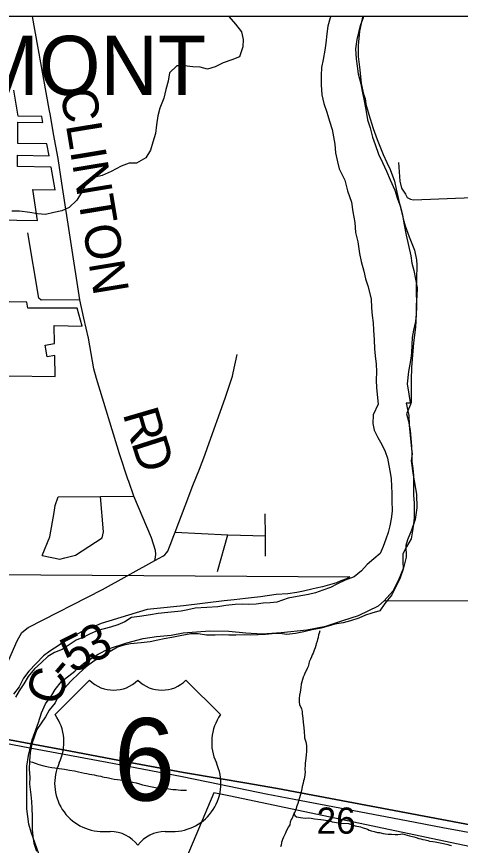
# Model space of a CAD drawing. Extents: x -8.5 to 18.7, y -20.3 to 7.
# Drawn here: x -4.185 to -2.768, y 4.29 to 6.938 of the extents above; entities that cross this region are included whole.
import ezdxf

# ---------------------------------------------------------------- set-up
doc = ezdxf.new("R2010")
doc.units = 0
for name, color, linetype in [('Default', 7, 'Continuous'), ('GM_X_City_Street', 7, 'Continuous'), ('GM_X_Corporation', 7, 'Continuous'), ('GM_X_Corporation_Text', 7, 'Continuous'), ('GM_X_County_Road', 7, 'Continuous'), ('GM_X_County_Road_Text', 7, 'Continuous'), ('GM_X_Major_River', 7, 'Continuous'), ('GM_X_Minor_River', 7, 'Continuous'), ('GM_X_Section', 7, 'Continuous'), ('GM_X_Section_Text', 7, 'Continuous'), ('GM_X_State_Route', 7, 'Continuous'), ('GM_X_Township_Road', 7, 'Continuous'), ('GM_X_US_Location', 7, 'Continuous'), ('GM_X_US_Route', 7, 'Continuous'), ('GM_X_US_Shield', 7, 'Continuous'), ('SH_Cut_Line', 7, 'Continuous')]:
    doc.layers.add(name, color=color, linetype=linetype)

msp = doc.modelspace()

# ---------------------------------------------------------------- linework, layer by layer
at = {"layer": 'Default'}
msp.add_lwpolyline([(-2.1387, 6.938), (-3.0796, 6.938), (-3.082, 6.9308), (-3.0906, 6.8915), (-3.0947, 6.846), (-3.0949, 6.8104), (-3.0899, 6.7679), (-3.0848, 6.7239), (-3.0775, 6.6905), (-3.073, 6.6761), (-3.0701, 6.6586), (-3.0604, 6.6252), (-3.0471, 6.5804), (-3.0344, 6.5455), (-3.015, 6.4976), (-3.003, 6.4717), (-2.9926, 6.4489), (-2.9791, 6.4117), (-2.9732, 6.3867), (-2.9659, 6.3533), (-2.96, 6.3267), (-2.9496, 6.2842), (-2.9444, 6.2697), (-2.9325, 6.234), (-2.9153, 6.1915), (-2.9087, 6.1611), (-2.908, 6.1452), (-2.9083, 6.0975), (-2.9092, 6.0724), (-2.9089, 6.008), (-2.9123, 5.9451), (-2.9187, 5.8951), (-2.922, 5.8436), (-2.9245, 5.8171), (-2.9255, 5.7777), (-2.9259, 5.7163), (-2.9252, 5.7026), (-2.9416, 5.7024), (-2.9327, 5.6637), (-2.9322, 5.6326), (-2.9243, 5.5567), (-2.9221, 5.5408), (-2.9253, 5.5181), (-2.9188, 5.4726), (-2.9085, 5.4118), (-2.9073, 5.3679), (-2.9128, 5.3315), (-2.9244, 5.2967), (-2.9375, 5.2665), (-2.9429, 5.2476), (-2.9416, 5.2104), (-2.9502, 5.1764), (-2.9671, 5.1355), (-2.9847, 5.1023), (-3.0114, 5.0714), (-2.2011, 5.074)], dxfattribs=at)
at = {"layer": 'GM_X_City_Street'}
for points in [[(-4.2512, 6.2886), (-4.1182, 6.2863), (-4.134, 6.3858), (-4.0618, 6.3844), (-4.0749, 6.4565), (-4.1821, 6.4584), (-4.1821, 6.4955), (-4.0818, 6.4935), (-4.0887, 6.5311), (-4.1813, 6.5328), (-4.1813, 6.601), (-4.1014, 6.5997), (-4.1049, 6.6189), (-4.1809, 6.6201), (-4.194, 6.7024)], [(-4.2097, 5.7905), (-4.0623, 5.788), (-4.0635, 5.8554), (-4.0882, 5.8511), (-4.0941, 5.8885), (-4.0642, 5.8938), (-4.0653, 5.9506), (-3.9758, 5.9491), (-3.9919, 6.0062), (-4.1498, 6.0064), (-4.1528, 6.0255), (-4.2096, 6.0265)], [(-2.7206, 4.2815), (-3.5022, 4.4472), (-3.5552, 4.4573), (-3.6617, 4.2047)]]:
    msp.add_lwpolyline(points, dxfattribs=at)
at = {"layer": 'GM_X_Corporation'}
msp.add_lwpolyline([(-0.1911, 6.938), (-8.4587, 6.938), (-8.4587, 1.1732)], dxfattribs=at)
at = {"layer": 'GM_X_County_Road'}
for p, q in [((-4.0811, 6.6417), (-4.1343, 6.938)), ((-4.0776, 6.6221), (-4.0811, 6.6417)), ((-4.0671, 6.5632), (-4.0776, 6.6221)), ((-4.06, 6.524), (-4.0671, 6.5632)), ((-4.053, 6.4848), (-4.06, 6.524)), ((-4.041, 6.4062), (-4.053, 6.4848)), ((-3.9839, 6.0329), (-4.041, 6.4062)), ((-3.9706, 5.9747), (-3.9839, 6.0329))]:
    msp.add_line(p, q, dxfattribs=at)
for points in [[(-3.9299, 5.7817), (-3.939, 5.812), (-3.9558, 5.9108), (-3.9706, 5.9747)], [(-3.8298, 5.4598), (-3.8574, 5.5413), (-3.9299, 5.7817)], [(-4.2363, 4.8324), (-4.2176, 4.8653), (-4.1837, 4.9433), (-4.1688, 4.9696), (-4.1488, 4.986), (-3.9115, 5.1068), (-3.7446, 5.2003), (-3.7418, 5.2105), (-3.7408, 5.2204), (-3.7415, 5.2315), (-3.7547, 5.2723), (-3.8114, 5.4057), (-3.8272, 5.4522), (-3.8298, 5.4598)]]:
    msp.add_lwpolyline(points, dxfattribs=at)
at = {"layer": 'GM_X_Major_River'}
for points in [[(-3.1825, 6.938), (-3.184, 6.9335), (-3.1913, 6.907), (-3.1948, 6.8827), (-3.1984, 6.8531), (-3.2018, 6.8303), (-3.2062, 6.8007), (-3.2119, 6.7757), (-3.2131, 6.7498), (-3.2129, 6.7194), (-3.2112, 6.6874), (-3.2048, 6.6598), (-3.1947, 6.6322), (-3.186, 6.6039), (-3.1774, 6.5771), (-3.1698, 6.5298), (-3.1673, 6.5031), (-3.1609, 6.474), (-3.1552, 6.4511), (-3.1376, 6.4157), (-3.1291, 6.3813), (-3.116, 6.3453), (-3.112, 6.314), (-3.1057, 6.2804), (-3.1033, 6.2476), (-3.0962, 6.2185), (-3.0908, 6.1811), (-3.0851, 6.1559), (-3.0765, 6.1245), (-3.0716, 6.1), (-3.0644, 6.0771), (-3.053, 6.0357), (-3.0527, 6.0076), (-3.0501, 5.9831), (-3.0475, 5.9595), (-3.0456, 5.9359), (-3.0439, 5.9054), (-3.0429, 5.8764), (-3.0402, 5.8535), (-3.0376, 5.8276), (-3.0365, 5.804), (-3.0378, 5.7766), (-3.0367, 5.7515), (-3.0307, 5.6993)], [(-3.0774, 6.938), (-3.079, 6.9338), (-3.087, 6.9111), (-3.0935, 6.8869), (-3.0992, 6.8642), (-3.1036, 6.8353), (-3.1011, 6.8033), (-3.0984, 6.7796), (-3.0951, 6.7552), (-3.0865, 6.7231), (-3.0816, 6.6994), (-3.0753, 6.6688), (-3.069, 6.6344)], [(-3.069, 6.6344), (-3.0649, 6.6085), (-3.057, 6.5824), (-3.0492, 6.5526), (-3.0405, 6.5296), (-3.0296, 6.4982), (-3.0171, 6.4721), (-3.0047, 6.4437), (-2.993, 6.416), (-2.9783, 6.383), (-2.9704, 6.3593), (-2.9595, 6.3301), (-2.9531, 6.3034), (-2.9476, 6.2728), (-2.9413, 6.2399), (-2.9343, 6.2063), (-2.9265, 6.1734), (-2.9231, 6.1505), (-2.9174, 6.1261), (-2.9118, 6.0985), (-2.907, 6.071), (-2.9074, 6.0452), (-2.9095, 6.0155), (-2.9092, 5.9873), (-2.9119, 5.9638), (-2.9177, 5.9365), (-2.922, 5.913), (-2.9231, 5.8894), (-2.9251, 5.8628), (-2.9278, 5.8392), (-2.9338, 5.8036), (-2.9383, 5.7648), (-2.9281, 5.6987)], [(-3.0307, 5.6993), (-3.047, 5.6654), (-3.048, 5.6381), (-3.0437, 5.6167), (-3.0319, 5.5931), (-3.0192, 5.5709), (-3.0089, 5.5488), (-3.0015, 5.5267), (-2.9972, 5.5031), (-2.9922, 5.4811), (-2.9894, 5.4605), (-2.9881, 5.4377), (-2.9876, 5.4142), (-2.9871, 5.3914), (-2.986, 5.358), (-2.9893, 5.333), (-2.9933, 5.311), (-2.9989, 5.289), (-3.0067, 5.2679), (-3.0153, 5.2452), (-3.0247, 5.2225), (-3.0454, 5.2053), (-3.0661, 5.1873), (-3.0845, 5.167), (-3.1075, 5.1482), (-3.1364, 5.1371), (-3.1631, 5.1245), (-3.1837, 5.1141), (-3.2081, 5.1053), (-3.231, 5.0971), (-3.253, 5.0913), (-3.2895, 5.0849), (-3.3184, 5.0799), (-3.355, 5.0666), (-3.3762, 5.0645), (-3.3983, 5.064), (-3.4203, 5.0605), (-3.4438, 5.0592), (-3.4651, 5.0602), (-3.4878, 5.0597), (-3.5175, 5.0562), (-3.5433, 5.0519), (-3.5782, 5.05), (-3.6154, 5.0473), (-3.639, 5.0423), (-3.6595, 5.0379), (-3.6816, 5.0359), (-3.7028, 5.0339), (-3.7332, 5.0304), (-3.7583, 5.0269), (-3.7925, 5.0211), (-3.8183, 5.0176), (-3.8397, 5.0042), (-3.8626, 4.9946), (-3.8854, 4.9872), (-3.906, 4.9821), (-3.9265, 4.9763), (-3.9502, 4.9659), (-3.9723, 4.9547), (-3.9952, 4.9451), (-4.0181, 4.9302), (-4.0403, 4.916), (-4.0639, 4.9064), (-4.0853, 4.8937), (-4.106, 4.8742), (-4.1282, 4.8539), (-4.1482, 4.8291), (-4.1621, 4.8064), (-4.1768, 4.7838), (-4.1884, 4.7634)], [(-2.9281, 5.6987), (-2.9407, 5.6688), (-2.9342, 5.6452), (-2.9292, 5.6155), (-2.9264, 5.5904), (-2.9245, 5.5638), (-2.924, 5.5395), (-2.9235, 5.5168), (-2.9199, 5.4939), (-2.9187, 5.4719), (-2.9182, 5.4499), (-2.9184, 5.4294), (-2.9179, 5.4074), (-2.9166, 5.3846), (-2.9162, 5.3603), (-2.9164, 5.3367), (-2.9182, 5.3163), (-2.9215, 5.295), (-2.9255, 5.2693), (-2.9402, 5.2436), (-2.9519, 5.2217), (-2.9521, 5.1982), (-2.9509, 5.1724), (-2.9611, 5.1451), (-2.9712, 5.1225), (-2.9875, 5.0908), (-3.0098, 5.0629), (-3.026, 5.0395), (-3.0512, 5.0315), (-3.0717, 5.0256), (-3.0931, 5.0152), (-3.1189, 5.0071), (-3.1425, 5.0013), (-3.1699, 4.997), (-3.1905, 4.9897), (-3.2125, 4.9838), (-3.2414, 4.9781), (-3.268, 4.9723), (-3.2954, 4.9665), (-3.3228, 4.9637), (-3.3447, 4.9663), (-3.3698, 4.9658), (-3.3903, 4.9637), (-3.4146, 4.9624), (-3.4374, 4.9619), (-3.4586, 4.9622), (-3.4852, 4.9609), (-3.5079, 4.9619), (-3.5292, 4.9622), (-3.5512, 4.9616), (-3.5792, 4.9619), (-3.6057, 4.9652), (-3.6293, 4.9655), (-3.6627, 4.959), (-3.6901, 4.954), (-3.7144, 4.9497), (-3.7349, 4.9454), (-3.7593, 4.9396), (-3.7881, 4.9368), (-3.8216, 4.9341), (-3.8428, 4.9298), (-3.8634, 4.9232), (-3.8863, 4.909), (-3.9154, 4.8919), (-3.939, 4.8785), (-3.9628, 4.8597), (-3.9857, 4.8395), (-4.0118, 4.8147), (-4.0326, 4.7921), (-4.0503, 4.7696), (-4.0627, 4.7454), (-4.0819, 4.7221), (-4.0935, 4.7009), (-4.1074, 4.6806), (-4.1206, 4.6595), (-4.1284, 4.6383), (-4.137, 4.6141), (-4.1419, 4.5868), (-4.1445, 4.5602), (-4.1455, 4.5322), (-4.1435, 4.5079), (-4.1445, 4.4851), (-4.1404, 4.4516), (-4.1383, 4.4304), (-4.1363, 4.4083), (-4.1359, 4.3825), (-4.1353, 4.3612), (-4.1356, 4.3407), (-4.1336, 4.3179), (-4.13, 4.2966), (-4.1219, 4.2707)]]:
    msp.add_lwpolyline(points, dxfattribs=at)
at = {"layer": 'GM_X_Minor_River'}
for points in [[(-3.5078, 6.938), (-3.4864, 6.914), (-3.4676, 6.8896), (-3.4617, 6.8644), (-3.4626, 6.8409), (-3.4742, 6.8098), (-3.4978, 6.8001), (-3.526, 6.7897), (-3.5511, 6.777), (-3.5762, 6.7696), (-3.5997, 6.7766), (-3.6232, 6.7776), (-3.6505, 6.7801), (-3.674, 6.7803), (-3.6977, 6.7585), (-3.7017, 6.7311), (-3.7094, 6.7046), (-3.7157, 6.6773), (-3.7281, 6.6455), (-3.7343, 6.6212), (-3.7391, 6.5923), (-3.7423, 6.5642), (-3.7501, 6.5369), (-3.7579, 6.5112), (-3.7732, 6.4862), (-3.8022, 6.4697), (-3.8265, 6.4699), (-3.8516, 6.4603), (-3.8836, 6.4431), (-3.9125, 6.4304), (-3.9391, 6.4238), (-3.9628, 6.4034), (-3.9782, 6.3754), (-3.9927, 6.3512), (-4.0172, 6.3279), (-4.0408, 6.3174), (-4.0666, 6.3123), (-4.0932, 6.3057), (-4.119, 6.3074), (-4.1433, 6.3122), (-4.1759, 6.3163), (-4.2001, 6.3157)], [(-3.2178, 4.9756), (-3.2195, 4.9673), (-3.2211, 4.962), (-3.2228, 4.9544), (-3.2252, 4.9476), (-3.2261, 4.9423), (-3.2293, 4.9333), (-3.2301, 4.928), (-3.2326, 4.9205), (-3.235, 4.9137), (-3.239, 4.9039), (-3.2414, 4.8987), (-3.2438, 4.8926), (-3.247, 4.8843), (-3.2509, 4.8761), (-3.2526, 4.8693), (-3.255, 4.861), (-3.2582, 4.855), (-3.2614, 4.8475), (-3.2653, 4.8399), (-3.2677, 4.8332), (-3.2701, 4.8271), (-3.275, 4.8121), (-3.2766, 4.8053), (-3.2784, 4.7939), (-3.2802, 4.7788), (-3.2827, 4.7697), (-3.2836, 4.7591), (-3.283, 4.7523), (-3.2831, 4.747), (-3.2818, 4.7394), (-3.276, 4.7256), (-3.2739, 4.718), (-3.274, 4.7111), (-3.2713, 4.6959), (-3.2701, 4.6822), (-3.2695, 4.6746), (-3.2669, 4.6548), (-3.267, 4.648), (-3.2664, 4.6419), (-3.2666, 4.6336), (-3.2644, 4.6275), (-3.2623, 4.6206), (-3.2595, 4.6084), (-3.2599, 4.5895), (-3.2609, 4.5789), (-3.2628, 4.5592), (-3.2637, 4.5539), (-3.2638, 4.5486), (-3.2649, 4.5311), (-3.2643, 4.5251), (-3.2652, 4.5152), (-3.267, 4.5016), (-3.2694, 4.4956), (-3.2703, 4.4888), (-3.2736, 4.4782), (-3.2745, 4.4706), (-3.2794, 4.4525), (-3.2835, 4.4382), (-3.2859, 4.4306), (-3.2876, 4.4239), (-3.2899, 4.4186), (-3.2916, 4.4126), (-3.2925, 4.4073), (-3.2964, 4.399), (-3.3028, 4.3847), (-3.3059, 4.3772), (-3.3091, 4.3719), (-3.3123, 4.3636), (-3.3132, 4.3553), (-3.3171, 4.3486), (-3.3242, 4.3373), (-3.3282, 4.3268), (-3.333, 4.3163), (-3.3362, 4.308), (-3.3394, 4.2989), (-3.3403, 4.2906), (-3.3427, 4.2846)], [(-4.1445, 4.5576), (-4.1344, 4.5553), (-4.1261, 4.5528), (-4.1141, 4.548), (-4.0983, 4.5439), (-4.0847, 4.5406), (-4.0734, 4.5381), (-4.0636, 4.5372), (-4.0492, 4.5354), (-4.0326, 4.5335), (-4.016, 4.5302), (-4.0009, 4.5276), (-3.9881, 4.5251), (-3.9783, 4.5226), (-3.9685, 4.5209), (-3.9617, 4.5192), (-3.9527, 4.5175), (-3.9451, 4.5166), (-3.9376, 4.5149), (-3.9308, 4.5133), (-3.924, 4.5124), (-3.9165, 4.5107), (-3.9112, 4.5091), (-3.9059, 4.5082), (-3.8976, 4.5066), (-3.8924, 4.5057), (-3.8833, 4.5032), (-3.8735, 4.5015), (-3.8637, 4.5006), (-3.8546, 4.4996), (-3.8463, 4.4979), (-3.8373, 4.497), (-3.8267, 4.4945), (-3.8154, 4.492), (-3.8033, 4.4895), (-3.7928, 4.4863), (-3.783, 4.483), (-3.7732, 4.4813), (-3.7574, 4.478), (-3.7423, 4.4746), (-3.7265, 4.472), (-3.7106, 4.471), (-3.6993, 4.47), (-3.6925, 4.4691), (-3.6864, 4.4682), (-3.6758, 4.468), (-3.6698, 4.4671), (-3.6607, 4.4662), (-3.6433, 4.4658)], [(-3.3018, 4.3945), (-3.2996, 4.3907), (-3.2975, 4.3854), (-3.2923, 4.3807), (-3.2855, 4.3798), (-3.2794, 4.3789), (-3.2719, 4.378), (-3.262, 4.3771), (-3.2545, 4.3777), (-3.2454, 4.3767), (-3.2341, 4.3742), (-3.2137, 4.3723), (-3.2061, 4.3714), (-3.1858, 4.368), (-3.1782, 4.3648), (-3.1564, 4.3613), (-3.1488, 4.3612), (-3.1254, 4.3592), (-3.1111, 4.3543), (-3.1043, 4.3519), (-3.0877, 4.3493), (-3.0817, 4.3469), (-3.0652, 4.3413), (-3.0599, 4.3381), (-3.0531, 4.3365), (-3.0441, 4.334), (-3.0336, 4.3308), (-3.0268, 4.3306), (-3.0155, 4.3282), (-3.0072, 4.3265), (-2.9996, 4.3256), (-2.9883, 4.3253), (-2.9769, 4.3243), (-2.9678, 4.3249), (-2.9602, 4.3255), (-2.9534, 4.3262), (-2.9459, 4.3245), (-2.9308, 4.3204), (-2.9173, 4.3171), (-2.9097, 4.3154), (-2.9007, 4.3122), (-2.8947, 4.3106), (-2.8879, 4.3089), (-2.8811, 4.3073), (-2.8728, 4.3056), (-2.8668, 4.3032), (-2.8562, 4.3022), (-2.8495, 4.3006), (-2.8336, 4.298), (-2.8276, 4.2971), (-2.8223, 4.2955), (-2.8087, 4.2922), (-2.8027, 4.2905), (-2.7967, 4.2897)]]:
    msp.add_lwpolyline(points, dxfattribs=at)
at = {"layer": 'GM_X_Section'}
for points in [[(-4.2745, 5.1557), (-3.1216, 5.1479), (-3.1285, 5.1426), (-3.1505, 5.1351), (-3.1642, 5.1284), (-3.209, 5.1158), (-3.2287, 5.1121), (-3.2386, 5.1091), (-3.2697, 5.1025), (-3.291, 5.0973), (-3.3198, 5.093), (-3.357, 5.0909), (-3.4063, 5.0836), (-3.4548, 5.0786), (-3.4912, 5.0743), (-3.5231, 5.0707), (-3.6528, 5.0556), (-3.7476, 5.0456), (-3.7681, 5.0434), (-3.8281, 5.0248), (-3.9154, 4.9989), (-3.9778, 4.972), (-4.0013, 4.9592), (-4.0249, 4.948), (-4.0493, 4.9292), (-4.079, 4.9104), (-4.0995, 4.8954), (-4.1461, 4.8464), (-4.1629, 4.8238), (-4.1774, 4.7958), (-4.195, 4.7724)], [(-4.1081, 4.2443), (-4.1394, 4.3324), (-4.1468, 4.3575), (-4.1525, 4.4068), (-4.153, 4.4606), (-4.1532, 4.5425), (-4.1469, 4.5773), (-4.136, 4.6273), (-4.116, 4.6825), (-4.1059, 4.7135), (-4.0929, 4.7422), (-4.073, 4.7694), (-4.0623, 4.7883), (-4.0417, 4.8132), (-3.999, 4.8462), (-3.9708, 4.8719), (-3.9251, 4.9004), (-3.8917, 4.9176), (-3.8332, 4.937), (-3.7816, 4.9503), (-3.7383, 4.9576), (-3.692, 4.9611), (-3.6541, 4.9684), (-3.5684, 4.9755), (-3.5078, 4.9744), (-3.4532, 4.9687), (-3.4009, 4.9661), (-3.341, 4.9695), (-3.2591, 4.9789), (-3.1984, 4.9899), (-3.1437, 5.0085), (-3.0936, 5.0241), (-3.0297, 5.0548), (-3.0114, 5.0714), (-2.2011, 5.074)]]:
    msp.add_lwpolyline(points, dxfattribs=at)
at = {"layer": 'GM_X_State_Route'}
msp.add_lwpolyline([(-2.5151, 4.3134), (-2.5309, 4.3165), (-2.7546, 4.3585), (-3.3528, 4.4711), (-3.4568, 4.4899), (-3.5327, 4.5028), (-3.6527, 4.523), (-3.7428, 4.5391), (-3.8177, 4.5532), (-4.0136, 4.5906), (-4.1567, 4.6172), (-4.2822, 4.6413)], dxfattribs=at)
at = {"layer": 'GM_X_Township_Road'}
for p, q in [((-3.4943, 5.7993), (-3.4815, 5.8585)), ((-3.5438, 5.1647), (-3.5108, 5.2824)), ((-3.3905, 5.2142), (-3.3908, 5.2592))]:
    msp.add_line(p, q, dxfattribs=at)
for points in [[(-2.9656, 6.4716), (-2.9618, 6.4121), (-2.9561, 6.3892), (-2.9442, 6.37), (-2.9385, 6.3603), (-2.9282, 6.3546), (-2.9178, 6.352), (-2.6225, 6.3637), (-2.4066, 6.3758)], [(-3.9839, 6.0329), (-4.1068, 6.0321), (-4.114, 6.0377), (-4.1491, 6.247)], [(-3.6858, 5.2742), (-3.6795, 5.2905), (-3.6473, 5.3743), (-3.6225, 5.4396), (-3.6016, 5.4918), (-3.5848, 5.5361), (-3.5756, 5.5609), (-3.5197, 5.7186), (-3.4965, 5.7895), (-3.4943, 5.7993)], [(-4.1041, 5.2155), (-4.0789, 5.2759), (-4.0655, 5.3532), (-4.0628, 5.3759), (-4.0525, 5.4031)], [(-4.0525, 5.4031), (-3.9177, 5.4046), (-3.8114, 5.4057)], [(-4.0313, 5.2086), (-3.9978, 5.2168), (-3.9126, 5.2725), (-3.9078, 5.2921), (-3.9177, 5.4046)], [(-3.3908, 5.2592), (-3.391, 5.2793), (-3.3915, 5.3492)], [(-3.7446, 5.2003), (-3.7307, 5.2074), (-3.7189, 5.2136), (-3.7125, 5.2183), (-3.7068, 5.2244), (-3.7026, 5.2301), (-3.69, 5.2633), (-3.6858, 5.2742)], [(-3.6795, 5.2905), (-3.5108, 5.2824), (-3.391, 5.2793)], [(-4.1041, 5.2155), (-4.0474, 5.2047), (-4.0313, 5.2086)]]:
    msp.add_lwpolyline(points, dxfattribs=at)
at = {"layer": 'GM_X_US_Route'}
for points in [[(-4.6555, 4.6934), (-4.6282, 4.6899), (-4.5897, 4.6841), (-4.4884, 4.6668), (-4.287, 4.6289), (-4.1658, 4.606), (-4.0572, 4.5855)], [(-4.2822, 4.6413), (-4.1567, 4.6172), (-4.0136, 4.5906), (-3.8177, 4.5532), (-3.7428, 4.5391), (-3.6527, 4.523), (-3.5327, 4.5028), (-3.4568, 4.4899), (-3.3528, 4.4711), (-2.7546, 4.3585), (-2.5309, 4.3165), (-2.5151, 4.3134)], [(-4.0572, 4.5855), (-4.0165, 4.5778), (-3.8966, 4.5554), (-3.807, 4.5384), (-3.6567, 4.5093), (-3.538, 4.4848), (-3.3887, 4.4543), (-3.2995, 4.4369), (-2.9404, 4.3693), (-2.8243, 4.3473)], [(-2.8243, 4.3473), (-2.7604, 4.3352), (-2.5512, 4.296)]]:
    msp.add_lwpolyline(points, dxfattribs=at)
at = {"layer": 'GM_X_US_Shield'}
for p, q in [((-3.9523, 4.8173), (-4.0622, 4.7074)), ((-3.5348, 4.7074), (-3.6447, 4.8173)), ((-3.9084, 4.3339), (-3.8864, 4.3339)), ((-3.7106, 4.3339), (-3.6886, 4.3339))]:
    msp.add_line(p, q, dxfattribs=at)
for centre, radius, start, end in [((-3.8754, 4.8957), 0.1099, 225.573, 314.427), ((-3.7216, 4.8957), 0.1099, 225.573, 314.427), ((-4.1882, 4.6192), 0.1538, 334.5471, 35.0009), ((-3.4088, 4.6192), 0.1538, 144.9991, 205.4529), ((-3.9101, 4.4877), 0.1538, 154.8319, 270.6383), ((-3.6869, 4.4877), 0.1538, 269.3617, 25.1681), ((-3.8864, 4.224), 0.1099, 36.8699, 90), ((-3.7106, 4.224), 0.1099, 90, 143.1301)]:
    msp.add_arc(centre, radius, start, end, dxfattribs=at)
at = {"layer": 'SH_Cut_Line'}
msp.add_lwpolyline([(18.7413, 6.938), (-8.4587, 6.938), (-8.4587, -10.6981)], dxfattribs=at)

# ---------------------------------------------------------------- texts
at = {"layer": 'GM_X_Corporation_Text'}
msp.add_text('FREMONT', height=0.18939, rotation=0, dxfattribs=at).set_placement((-4.8322, 6.6871))
at = {"layer": 'GM_X_County_Road_Text'}
for s, height, rotation, p in [('CLINTON', 0.11364, 279.3643, (-4.0463, 6.7003)), ('R', 0.1136, 286.3239, (-3.8472, 5.6692)), ('D', 0.1136, 287.7514, (-3.8201, 5.5767)), ('3', 0.1136, 27.0124, (-3.9457, 4.869)), ('5', 0.1136, 26.8142, (-4.0081, 4.8375)), ('-', 0.1136, 49.7612, (-4.0285, 4.8096)), ('C', 0.1136, 73.0338, (-4.0498, 4.7316))]:
    msp.add_text(s, height=height, rotation=rotation, dxfattribs=at).set_placement(p)
at = {"layer": 'GM_X_Section_Text'}
msp.add_text('26', height=0.08371, rotation=0, dxfattribs=at).set_placement((-3.2277, 4.327))
at = {"layer": 'GM_X_US_Location'}
for s in ['0', '/']:
    msp.add_text(s, height=0.000379, dxfattribs=at).set_placement((-3.7986, 4.5625))
msp.add_text('6', height=0.000379, rotation=0, dxfattribs=at).set_placement((-3.8368, 4.4841))
at = {"layer": 'GM_X_US_Shield'}
msp.add_text('6', height=0.2637, dxfattribs=at).set_placement((-3.8751, 4.4327))

doc.saveas('drawing.dxf')
